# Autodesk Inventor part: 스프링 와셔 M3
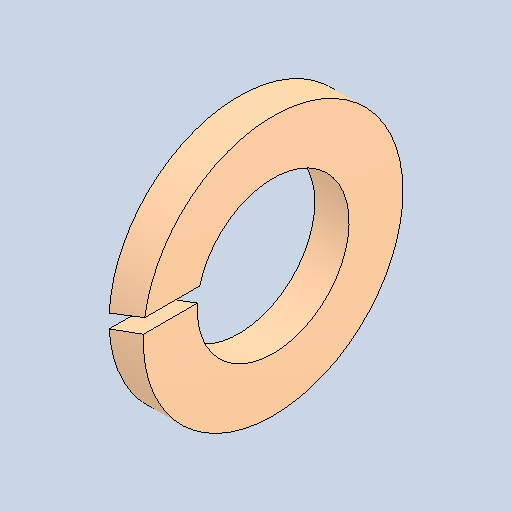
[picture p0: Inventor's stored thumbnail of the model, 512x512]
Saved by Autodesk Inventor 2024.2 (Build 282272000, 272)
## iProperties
Created: 2025-09
Part Number: 스프링 와셔 M3
Material: 강철, 연강
Description: 스프링 잠금 와셔
Document SubType Name: Modeling
Designer: home
Density: 7.85 g/cm^3
Appearance: 기본값
Author: jhkim
Sending System: Autodesk Inventor 2026
Preprocessor: ST-DEVELOPER v20.1
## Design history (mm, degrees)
feature "Solid1"
node "솔리드1"
